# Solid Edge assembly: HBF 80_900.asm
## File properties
Title: Zylinder
Author: ahadarics
Template: iso assembly.asm
Last saved by: ahadarics
Revision: 52
Application: Solid Edge
Username: ahadarics
Dokumentum tartalom típus: 1
Document Number: HBF 80/900
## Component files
Kit.par
Profilrohr 80_900.par
Kolbenstange_1_80_900.par
Mutter.par
Kolbenstange_2_80_900.par
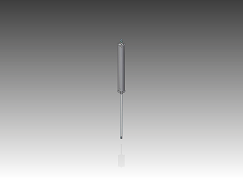
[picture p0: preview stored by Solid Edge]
